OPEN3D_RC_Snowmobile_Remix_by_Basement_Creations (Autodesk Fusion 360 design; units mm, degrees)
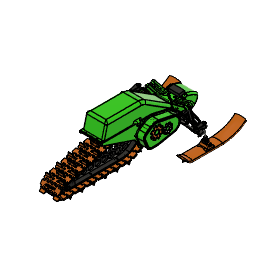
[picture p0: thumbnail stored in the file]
part number: m5x30
part number: m5 locknut (7)
part number: m5x40 (1)
part number: right ski hinge
part number: right steering block
part number: right suspension block
part number: left ski hinge
part number: left outer steering arm
part number: left suspension block
part number: left steering block
part number: right outer steering arm
part number: rear shock mount
part number: track lower ptfe rail 3
part number: left track tensioning block
part number: track hardware
part number: right track tensioning block
part number: right track tensioner
part number: left track tensioner
part number: track lower ptfe rail 2
part number: track spacer right
derived_base_feature "Derived Base Feature1" bodies "Cover", "Frame 1 (1) (1)", "Gears Cover", "Front Cover", "Center Frame", "Top Cover"
extrude "Extrude1" cut of existing geometry blind -2
sketch "Sketch1" plane through (-63, 0, 0) normal (-1, 0, 0) x axis (0, 0, 1)
  line L1 (-98.8345, -25) -> (-74.8119, -25)
  line L2 (-109.7, -25) -> (-113.5655, -25)
  line L3 (-109.7, -28.5) -> (-109.7, -25)
  line L4 (-71.8, -28.5) -> (-109.7, -28.5)
  line L5 (-58.8, 16.6785) -> (-58.8, -15.5)
  line L6 (-30.4282, 38.5) -> (-31.5, 38.5)
  line L7 (14.5718, 38.5) -> (-16.5718, 38.5)
  line L8 (134.5718, 38.5) -> (28.4282, 38.5)
  line L9 (148.1, 42.5) -> (148.1, 38.5)
  line L10 (-31.5, 42.5) -> (148.1, 42.5)
  line L11 (-113.5, 26) -> (-70.1426, 26)
  line L12 (-113.5, 22) -> (-113.5, 26)
  line L13 (-106.8655, 22) -> (-113.5, 22)
  line L14 (-62, -15.1881) -> (-62, -14.4914)
  line L15 (13.9646, 38.5) -> (13.9646, 42.5)
  line L16 (29.9755, 38.5) -> (29.9755, 42.5)
  line L17 (13.5961, 42.5) -> (13.9646, 42.5)
  line L18 (10, 38.5) -> (10, 42.5)
  line L19 (37, 42.5) -> (29.9755, 42.5)
  line L20 (37, 38.5) -> (37, 42.5)
  arc A1 centre (-70.9691, -27.6881) radius 3.5 clockwise from (-72.3848, -24.4872) to (-71.997, -24.3424)
  arc A2 centre (-74.8119, -19) radius 6 clockwise from (-72.3848, -24.4872) to (-74.8119, -25)
  arc A3 centre (-98.8345, -19) radius 6 clockwise from (-98.8345, -25) to (-103.4864, -22.7895)
  arc A4 centre (-106.2, -25) radius 3.5 clockwise from (-108.9136, -22.7895) to (-103.4864, -22.7895)
  arc A5 centre (-113.5655, -19) radius 6 clockwise from (-108.9136, -22.7895) to (-113.5655, -25)
  arc A6 centre (-71.8, -15.5) radius 13 clockwise from (-58.8, -15.5) to (-71.8, -28.5)
  arc A7 centre (-43.8, 16.6785) radius 15 clockwise from (-58.8, 16.6785) to (-56.5241, 24.6219)
  arc A8 centre (-31.5, 9) radius 29.5 clockwise from (-56.5241, 24.6219) to (-31.5, 38.5)
  arc A9 centre (-30.4282, 32.5) radius 6 clockwise from (-30.4282, 38.5) to (-26.0525, 36.6053)
  arc A10 centre (-23.5, 39) radius 3.5 clockwise from (-20.9475, 36.6053) to (-26.0525, 36.6053)
  arc A11 centre (-16.5718, 32.5) radius 6 clockwise from (-20.9475, 36.6053) to (-16.5718, 38.5)
  arc A12 centre (14.5718, 32.5) radius 6 clockwise from (14.5718, 38.5) to (18.9475, 36.6053)
  arc A13 centre (21.5, 39) radius 3.5 clockwise from (24.0525, 36.6053) to (18.9475, 36.6053)
  arc A14 centre (28.4282, 32.5) radius 6 clockwise from (24.0525, 36.6053) to (28.4282, 38.5)
  arc A15 centre (134.5718, 32.5) radius 6 clockwise from (134.5718, 38.5) to (138.9475, 36.6053)
  arc A16 centre (141.5, 39) radius 3.5 clockwise from (144.0558, 36.6088) to (138.9475, 36.6053)
  arc A17 centre (148.4371, 32.5095) radius 6 clockwise from (144.0558, 36.6088) to (148.1, 38.5)
  arc A18 centre (-31.5, 9) radius 33.5 clockwise from (-55.6968, 32.1682) to (-31.5, 42.5)
  arc A19 centre (-70.1426, 46) radius 20 clockwise from (-55.6968, 32.1682) to (-70.1426, 26)
  arc A20 centre (-106.8655, 16) radius 6 clockwise from (-106.8655, 22) to (-102.2136, 19.7895)
  arc A21 centre (-99.5, 22) radius 3.5 clockwise from (-96.7864, 19.7895) to (-102.2136, 19.7895)
  arc A22 centre (-92.1345, 16) radius 6 clockwise from (-96.7864, 19.7895) to (-93.0286, 21.933)
  arc A23 centre (-96.7537, 46.6539) radius 25 clockwise from (-89.9219, 22.6055) to (-93.0286, 21.933)
  arc A24 centre (-83.5, 0) radius 23.5 clockwise from (-89.9219, 22.6055) to (-78.78, 23.0211)
  arc A25 centre (-18.5241, 316.9075) radius 300 clockwise from (-66.3937, 20.7513) to (-78.78, 23.0211)
  arc A26 centre (-67, 17) radius 3.8 clockwise from (-66.3937, 20.7513) to (-63.2685, 17.718)
  arc A27 centre (231.3272, 74.4048) radius 300 clockwise from (-60.63, 5.405) to (-63.2685, 17.718)
  arc A28 centre (-83.5, 0) radius 23.5 clockwise from (-60.63, 5.405) to (-60.8785, -6.3654)
  arc A29 centre (-32, -14.4914) radius 30 clockwise from (-62, -14.4914) to (-60.8785, -6.3654)
  arc A30 centre (-71, -15.1881) radius 9 clockwise from (-62, -15.1881) to (-62.1826, -16.9917)
  arc A31 centre (-66.1014, -16.1901) radius 4 clockwise from (-62.1826, -16.9917) to (-66.2989, -20.1852)
  arc A32 centre (-66.4645, -23.5355) radius 3.3544 clockwise from (-69.5237, -22.1596) to (-66.2989, -20.1852)
  arc A33 centre (-73.1717, -20.5188) radius 4 clockwise from (-69.5237, -22.1596) to (-71.997, -24.3424)
  circle C1 centre (-62.7077, 21.9108) radius 1.4
  circle C2 centre (-23.5, 39) radius 1.4
  circle C3 centre (21.5, 39) radius 1.4
  circle C4 centre (-99.5, 22) radius 1.4
  circle C5 centre (141.5, 39) radius 1.4
  circle C6 centre (-66.4645, -23.5355) radius 1.4
  circle C7 centre (-106.2, -25) radius 1.4
  point P81 (13.9646, 42.5)
  point P82 (13.9646, 38.5)
  point P83 (29.9755, 42.5)
  point P84 (29.9755, 38.5)
  point P85 (13.5961, 42.5)
  point P86 (10, 42.5)
  point P87 (10, 38.5)
  point P88 (37, 42.5)
  point P89 (37, 38.5)
  coincident L10 P81
  coincident L7 P82
  perpendicular L7 L15
  coincident L10 P83
  coincident L8 P84
  perpendicular L8 L16
  coincident L10 P85
  coincident L10 P86
  coincident L7 P87
  perpendicular L7 L18
  coincident L10 P88
  coincident L8 P89
  perpendicular L8 L20
extrude "Extrude2" cut sketch "Sketch1" profile of L7 L8 L10 L15 L16 L17 L18 L19 L20 against normal blind 20
sketch "Sketch2" plane through (0, 38.5, 0) normal (0, -1, 0) x axis (1, 0, 0)
  line L1 (-63, 29.9755) -> (-43, 29.9755)
  line L2 (-63, 28.4282) -> (-63, 29.9755)
  line L3 (-51, 28.4282) -> (-63, 28.4282)
  line L4 (-51, 21.8646) -> (-51, 28.4282)
  line L5 (-51, 21.1354) -> (-51, 21.8646)
  line L6 (-51, 14.5718) -> (-51, 21.1354)
  line L7 (-63, 14.5718) -> (-51, 14.5718)
  line L8 (-63, 13.9646) -> (-63, 14.5718)
  line L9 (-43, 13.9646) -> (-63, 13.9646)
  line L10 (-43, 10) -> (-43, 13.9646)
  line L11 (-63, 10) -> (-43, 10)
  line L12 (-63, -16.5718) -> (-63, 10)
  line L13 (-51, -16.5718) -> (-63, -16.5718)
  line L14 (-51, -23.1354) -> (-51, -16.5718)
  line L15 (-51, -23.8646) -> (-51, -23.1354)
  line L16 (-51, -30.4282) -> (-51, -23.8646)
  line L17 (-63, -30.4282) -> (-51, -30.4282)
  line L18 (-63, -31.5) -> (-63, -30.4282)
  line L19 (13, -31.5) -> (-63, -31.5)
  line L20 (13, -8.9627) -> (13, -31.5)
  line L21 (9, -8.9627) -> (13, -8.9627)
  curve K1 (6, -2.7177) -> (9, -8.9627)
  line L22 (6, -2.6231) -> (6, -2.7177)
  curve K2 (9, 3.6219) -> (6, -2.6231)
  line L23 (13, 3.6219) -> (9, 3.6219)
  line L24 (13, 148.1) -> (13, 3.6219)
  line L25 (-51.1685, 148.1) -> (13, 148.1)
  curve K3 (-51, 148.0242) -> (-51.1685, 148.1)
  line L26 (-51, 141.8651) -> (-51, 148.0242)
  line L27 (-51, 141.1354) -> (-51, 141.8651)
  line L28 (-51, 134.5718) -> (-51, 141.1354)
  line L29 (-63, 134.5718) -> (-51, 134.5718)
  line L30 (-63, 37) -> (-63, 134.5718)
  line L31 (-43, 37) -> (-63, 37)
  line L32 (-43, 29.9755) -> (-43, 37)
  line L33 (-43, 11.9823) -> (-43, 33.4878)
  line L34 (-46, 11.9823) -> (-43, 11.9823)
  line L35 (-46, 33.4878) -> (-46, 11.9823)
  line L36 (-43, 33.4878) -> (-46, 33.4878)
  circle C1 centre (-5, 144.6) radius 1.4
  circle C2 centre (-45, 144.6) radius 1.4
  point P40 (-43, 11.9823)
  point P39 (-43, 33.4878)
  perpendicular L33 L34
  parallel L33 L35
  parallel L34 L36
  midpoint L10 P40
  perpendicular L9 L33
  midpoint L32 P39
extrude "Extrude3" cut sketch "Sketch2" profile of L1 L9 L10 L32 L33 L34 L35 L36 against normal blind 4 bodies "Center Frame"
move "Move1"
combine "Combine1" bodies "Center Frame"
extrude "Extrude4" add of existing geometry blind 3
extrude "Extrude5" add of existing geometry blind 17
derived_base_feature "Derived Base Feature1"
derived_base_feature "Derived Base Feature1"
derived_base_feature "Derived Base Feature1"
derived_base_feature "Derived Base Feature1" bodies "Body1"
derived_base_feature "Derived Base Feature1" bodies "Body1"
derived_base_feature "Derived Base Feature1" bodies "Body1"
derived_base_feature "Derived Base Feature1" bodies "Body1"
derived_base_feature "Derived Base Feature1" bodies "Body1"
derived_base_feature "Derived Base Feature1" bodies "Body1"
derived_base_feature "Derived Base Feature1" bodies "Body1"
derived_base_feature "Derived Base Feature1" bodies "Body1"
derived_base_feature "Derived Base Feature1" bodies "Body1"
derived_base_feature "Derived Base Feature1" bodies "Body1"
derived_base_feature "Derived Base Feature1" bodies "Body1"
derived_base_feature "Derived Base Feature1" bodies "Body1"
derived_base_feature "Derived Base Feature1" bodies "Body1"
derived_base_feature "Derived Base Feature1" bodies "Body1"
derived_base_feature "Derived Base Feature1" bodies "Body1"
derived_base_feature "Derived Base Feature1" bodies "Body1"
derived_base_feature "Derived Base Feature1" bodies "Body1"
derived_base_feature "Derived Base Feature1" bodies "Body1"
derived_base_feature "Derived Base Feature1" bodies "Body1"
derived_base_feature "Derived Base Feature1" bodies "Body1"
derived_base_feature "Derived Base Feature1" bodies "Body1"
derived_base_feature "Derived Base Feature1" bodies "Body1"
derived_base_feature "Derived Base Feature1" bodies "Body1"
derived_base_feature "Derived Base Feature1" bodies "Body1"
derived_base_feature "Derived Base Feature1" bodies "Body1"
derived_base_feature "Derived Base Feature1" bodies "Body1"
derived_base_feature "Derived Base Feature1" bodies "Body1"
derived_base_feature "Derived Base Feature1" bodies "Body1"
derived_base_feature "Derived Base Feature1" bodies "Body1"
derived_base_feature "Derived Base Feature1" bodies "Body1"
derived_base_feature "Derived Base Feature1" bodies "Body1"
derived_base_feature "Derived Base Feature1" bodies "Body1"
derived_base_feature "Derived Base Feature1" bodies "Body1"
derived_base_feature "Derived Base Feature1" bodies "Body1"
derived_base_feature "Derived Base Feature1" bodies "Body1"
derived_base_feature "Derived Base Feature1" bodies "Body1"
derived_base_feature "Derived Base Feature1" bodies "Body1"
derived_base_feature "Derived Base Feature1" bodies "Body1"
derived_base_feature "Derived Base Feature1" bodies "Body1"
derived_base_feature "Derived Base Feature1" bodies "Body1"
derived_base_feature "Derived Base Feature1" bodies "Body1"
derived_base_feature "Derived Base Feature1" bodies "Body1"
derived_base_feature "Derived Base Feature1" bodies "Body1"
derived_base_feature "Derived Base Feature1" bodies "Body1"
derived_base_feature "Derived Base Feature1" bodies "Body1"
derived_base_feature "Derived Base Feature1" bodies "Body1"
derived_base_feature "Derived Base Feature1" bodies "Body1"
derived_base_feature "Derived Base Feature1" bodies "Body1"
derived_base_feature "Derived Base Feature1" bodies "Body1"
derived_base_feature "Derived Base Feature1" bodies "Body1"
derived_base_feature "Derived Base Feature1"
derived_base_feature "Derived Base Feature1" bodies "Body1"
derived_base_feature "Derived Base Feature1" bodies "Body1"
derived_base_feature "Derived Base Feature1" bodies "Body1"
derived_base_feature "Derived Base Feature1" bodies "Body1"
derived_base_feature "Derived Base Feature1"
derived_base_feature "Derived Base Feature1" bodies "Body1"
derived_base_feature "Derived Base Feature1" bodies "Body1"
derived_base_feature "Derived Base Feature1" bodies "Body1"
derived_base_feature "Derived Base Feature1" bodies "Body1"
derived_base_feature "Derived Base Feature1" bodies "Body1"
derived_base_feature "Derived Base Feature1" bodies "Body1"
derived_base_feature "Derived Base Feature1" bodies "Body1"
derived_base_feature "Derived Base Feature1" bodies "Body1"
derived_base_feature "Derived Base Feature1" bodies "Body1"
derived_base_feature "Derived Base Feature1" bodies "Body1"
derived_base_feature "Derived Base Feature1" bodies "Body1"
derived_base_feature "Derived Base Feature1" bodies "Body1"
derived_base_feature "Derived Base Feature1" bodies "Body1"
derived_base_feature "Derived Base Feature1" bodies "Body1"
derived_base_feature "Derived Base Feature1" bodies "Body1"
derived_base_feature "Derived Base Feature1" bodies "Body1"
derived_base_feature "Derived Base Feature1" bodies "Body1"
derived_base_feature "Derived Base Feature1" bodies "Body1"
derived_base_feature "Derived Base Feature1" bodies "Body1"
derived_base_feature "Derived Base Feature1" bodies "Body1"
derived_base_feature "Derived Base Feature1" bodies "Body1"
derived_base_feature "Derived Base Feature1" bodies "Body1"
derived_base_feature "Derived Base Feature1" bodies "Body1"
derived_base_feature "Derived Base Feature1" bodies "Body1"
derived_base_feature "Derived Base Feature1" bodies "Body1"
derived_base_feature "Derived Base Feature1" bodies "Body1"
derived_base_feature "Derived Base Feature1" bodies "Body1"
derived_base_feature "Derived Base Feature1" bodies "Body1"
derived_base_feature "Derived Base Feature1" bodies "Body1"
derived_base_feature "Derived Base Feature1" bodies "Body1"
derived_base_feature "Derived Base Feature1" bodies "Body1"
derived_base_feature "Derived Base Feature1" bodies "Body1"
derived_base_feature "Derived Base Feature1" bodies "Body1"
derived_base_feature "Derived Base Feature1" bodies "Body1"
derived_base_feature "Derived Base Feature1" bodies "Body1"
derived_base_feature "Derived Base Feature1"
derived_base_feature "Derived Base Feature1" bodies "Body1"
derived_base_feature "Derived Base Feature1" bodies "Body1"
derived_base_feature "Derived Base Feature1" bodies "Body1"
derived_base_feature "Derived Base Feature1" bodies "Body1"
derived_base_feature "Derived Base Feature1" bodies "Body1"
derived_base_feature "Derived Base Feature1" bodies "Body1"
derived_base_feature "Derived Base Feature1" bodies "Body1"
derived_base_feature "Derived Base Feature1" bodies "Body1"
derived_base_feature "Derived Base Feature1" bodies "Body1"
derived_base_feature "Derived Base Feature1" bodies "Body1"
derived_base_feature "Derived Base Feature1" bodies "Body1"
place_component sketch "Sketch3"
derived_base_feature "Derived Base Feature1" sketch "Sketch3" bodies "Body1"
derived_base_feature "Derived Base Feature1" bodies "Body1"
derived_base_feature "Derived Base Feature1" bodies "Body1"
derived_base_feature "Derived Base Feature1" bodies "Body1"
derived_base_feature "Derived Base Feature1" bodies "Body1"
derived_base_feature "Derived Base Feature1"
derived_base_feature "Derived Base Feature1" bodies "Body1"
derived_base_feature "Derived Base Feature1" bodies "Body1"
derived_base_feature "Derived Base Feature1" bodies "Body1"
derived_base_feature "Derived Base Feature1" bodies "Body1"
derived_base_feature "Derived Base Feature1" bodies "Body1"
derived_base_feature "Derived Base Feature1" bodies "Body1"
derived_base_feature "Derived Base Feature1" bodies "Body1"
derived_base_feature "Derived Base Feature1" bodies "Body1"
derived_base_feature "Derived Base Feature1" bodies "Body1"
derived_base_feature "Derived Base Feature1" bodies "Body1"
derived_base_feature "Derived Base Feature1" bodies "Body1"
derived_base_feature "Derived Base Feature1" bodies "Body1"
derived_base_feature "Derived Base Feature1" bodies "Body1"
derived_base_feature "Derived Base Feature1" bodies "Body1"
derived_base_feature "Derived Base Feature1" bodies "Body1"
derived_base_feature "Derived Base Feature1" bodies "Body1"
derived_base_feature "Derived Base Feature1" bodies "Body1"
derived_base_feature "Derived Base Feature1" bodies "Body1"
derived_base_feature "Derived Base Feature1" bodies "Body1"
derived_base_feature "Derived Base Feature1" bodies "Body1"
derived_base_feature "Derived Base Feature1" bodies "Body1"
derived_base_feature "Derived Base Feature1" bodies "Body1"
derived_base_feature "Derived Base Feature1" bodies "Body1"
derived_base_feature "Derived Base Feature1" bodies "Body1"
derived_base_feature "Derived Base Feature1" bodies "Body1"
derived_base_feature "Derived Base Feature1" bodies "Body1"
derived_base_feature "Derived Base Feature1" bodies "Body1"
derived_base_feature "Derived Base Feature1" bodies "Body1"
derived_base_feature "Derived Base Feature1" bodies "Body1"
derived_base_feature "Derived Base Feature1" bodies "Body1"
derived_base_feature "Derived Base Feature1" bodies "Body1"
derived_base_feature "Derived Base Feature1" bodies "Body1"
derived_base_feature "Derived Base Feature1" bodies "Body1"
derived_base_feature "Derived Base Feature1" bodies "Body1"
derived_base_feature "Derived Base Feature1" bodies "Body1"
derived_base_feature "Derived Base Feature1" bodies "Body1"
derived_base_feature "Derived Base Feature1" bodies "Body1"
derived_base_feature "Derived Base Feature1" bodies "Body1"
derived_base_feature "Derived Base Feature1" bodies "Body1"
derived_base_feature "Derived Base Feature1" bodies "Body1"
derived_base_feature "Derived Base Feature1" bodies "Body1"
derived_base_feature "Derived Base Feature1" bodies "Body1"
derived_base_feature "Derived Base Feature1" bodies "Body1"
derived_base_feature "Derived Base Feature1" bodies "Body1"
derived_base_feature "Derived Base Feature1" bodies "Body1"
derived_base_feature "Derived Base Feature1" bodies "Body1"
derived_base_feature "Derived Base Feature1" bodies "Body1"
derived_base_feature "Derived Base Feature1" bodies "Body1"
derived_base_feature "Derived Base Feature1" bodies "Body1"
derived_base_feature "Derived Base Feature1" bodies "Body1"
derived_base_feature "Derived Base Feature1" bodies "Body1"
derived_base_feature "Derived Base Feature1" bodies "Body1"
derived_base_feature "Derived Base Feature1" bodies "Body1"
derived_base_feature "Derived Base Feature1" bodies "Body1"
derived_base_feature "Derived Base Feature1"
derived_base_feature "Derived Base Feature1" bodies "Body1"
derived_base_feature "Derived Base Feature1" bodies "Body1"
derived_base_feature "Derived Base Feature1" bodies "Body1"
derived_base_feature "Derived Base Feature1" bodies "Body1"
derived_base_feature "Derived Base Feature1" bodies "Body1"
derived_base_feature "Derived Base Feature1" bodies "Body1"
derived_base_feature "Derived Base Feature1" bodies "Body1"
derived_base_feature "Derived Base Feature1" bodies "Body1"
derived_base_feature "Derived Base Feature1" bodies "Body1"
derived_base_feature "Derived Base Feature1" bodies "Body1"
derived_base_feature "Derived Base Feature1" bodies "Body1"
derived_base_feature "Derived Base Feature1" bodies "Body1"
derived_base_feature "Derived Base Feature1" bodies "Body1"
derived_base_feature "Derived Base Feature1" bodies "Body1"
derived_base_feature "Derived Base Feature1" bodies "Body1"
derived_base_feature "Derived Base Feature1" bodies "Body1"
derived_base_feature "Derived Base Feature1"
derived_base_feature "Derived Base Feature1" bodies "Body1"
derived_base_feature "Derived Base Feature1" bodies "Body1"
derived_base_feature "Derived Base Feature1" bodies "Body1"
derived_base_feature "Derived Base Feature1" bodies "Body1"
derived_base_feature "Derived Base Feature1" bodies "Body1"
derived_base_feature "Derived Base Feature1" bodies "Body1"
derived_base_feature "Derived Base Feature1" bodies "Body1"
derived_base_feature "Derived Base Feature1" bodies "Body1"
derived_base_feature "Derived Base Feature1" bodies "Body1"
derived_base_feature "Derived Base Feature1" bodies "Body1"
derived_base_feature "Derived Base Feature1" bodies "Body1"
derived_base_feature "Derived Base Feature1" bodies "Body1"
derived_base_feature "Derived Base Feature1" bodies "Body1"
derived_base_feature "Derived Base Feature1" bodies "Body1"
derived_base_feature "Derived Base Feature1" bodies "Body1"
derived_base_feature "Derived Base Feature1" bodies "Body1"
sketch "Sketch3" plane through (0, 32.5, 0) normal (0, 1, 0) x axis (-1, 0, 0)
  line L1 (53, -116.699) -> (46.1312, -121.5476)
  line L2 (53, -113.4468) -> (53, -116.699)
  line L3 (-3, -113.4468) -> (53, -113.4468)
  line L4 (-3, -116.699) -> (-3, -113.4468)
  line L5 (3.8688, -121.5476) -> (-3, -116.699)
  arc A1 centre (25, -135.1) radius 3.4 clockwise from (21.7517, -134.0956) to (28.2483, -134.0956)
  arc A2 centre (39.8661, -137.1) radius 12 clockwise from (28.2483, -134.0956) to (39.3465, -125.1113)
  arc A3 centre (39.0001, -117.1188) radius 8 clockwise from (44.6206, -122.8117) to (39.3465, -125.1113)
  arc A4 centre (53.0514, -131.3512) radius 12 clockwise from (44.6206, -122.8117) to (46.1312, -121.5476)
  arc A5 centre (-3.0514, -131.3512) radius 12 clockwise from (3.8688, -121.5476) to (5.3794, -122.8117)
  arc A6 centre (10.9999, -117.1188) radius 8 clockwise from (10.6535, -125.1113) to (5.3794, -122.8117)
  arc A7 centre (10.1339, -137.1) radius 12 clockwise from (10.6535, -125.1113) to (21.7517, -134.0956)
  circle C1 centre (25, -135.1) radius 1.4
  concentric A1 C1
  dimension "d11" diameter C1 = 2.8
extrude "Extrude6" cut sketch "Sketch3" profile of C1 against normal blind 20
derived_base_feature "Derived Base Feature2" bodies "8mm Aluminium Pipe", "Motor", "Big Gear", "Rear Sprocket Arm Left"
derived_base_feature "Derived Base Feature3" bodies "Small Motor Gear"
extrude "Extrude7" new body of existing geometry blind 3 bodies "Left Center Frame"
move "Move2"
extrude "Extrude8" new body of existing geometry blind 3
move "Move3"
sketch "Sketch4" plane through (-63, 0, 0) normal (-1, 0, 0) x axis (0, 0, 1)
  line L1 (134.5718, 38.5) -> (41.4282, 38.5)
  line L2 (148.1, 42.5) -> (148.1, 38.5)
  line L3 (-31.5, 42.5) -> (148.1, 42.5)
  line L4 (-113.5, 26) -> (-70.1426, 26)
  line L5 (-113.5, 22) -> (-113.5, 26)
  line L6 (-106.8655, 22) -> (-113.5, 22)
  line L7 (-62, -15.1881) -> (-62, -14.4914)
  line L8 (-98.8345, -25) -> (-74.8119, -25)
  line L9 (-109.7, -25) -> (-113.5655, -25)
  line L10 (-109.7, -28.5) -> (-109.7, -25)
  line L11 (-71.8, -28.5) -> (-109.7, -28.5)
  line L12 (-58.8, 16.6785) -> (-58.8, -15.5)
  line L13 (-30.4282, 38.5) -> (-31.5, 38.5)
  line L14 (27.5718, 38.5) -> (-16.5718, 38.5)
  line L15 (-28.044, 38.006) -> (148.1, 38.5)
  circle C1 centre (-106.2, -25) radius 1.4
  circle C2 centre (-66.4645, -23.5355) radius 1.4
  circle C3 centre (-99.5, 22) radius 1.4
  circle C4 centre (-23.5, 39) radius 1.4
  circle C5 centre (-62.7077, 21.9108) radius 1.4
  circle C6 centre (34.5, 39) radius 1.4
  arc A1 centre (134.5718, 32.5) radius 6 clockwise from (134.5718, 38.5) to (138.9475, 36.6053)
  arc A2 centre (141.5, 39) radius 3.5 clockwise from (144.0558, 36.6088) to (138.9475, 36.6053)
  arc A3 centre (148.4371, 32.5095) radius 6 clockwise from (144.0558, 36.6088) to (148.1, 38.5)
  arc A4 centre (-31.5, 9) radius 33.5 clockwise from (-55.6968, 32.1682) to (-31.5, 42.5)
  arc A5 centre (-70.1426, 46) radius 20 clockwise from (-55.6968, 32.1682) to (-70.1426, 26)
  arc A6 centre (-106.8655, 16) radius 6 clockwise from (-106.8655, 22) to (-102.2136, 19.7895)
  arc A7 centre (-99.5, 22) radius 3.5 clockwise from (-96.7864, 19.7895) to (-102.2136, 19.7895)
  arc A8 centre (-92.1345, 16) radius 6 clockwise from (-96.7864, 19.7895) to (-93.0286, 21.933)
  arc A9 centre (-96.7537, 46.6539) radius 25 clockwise from (-89.9219, 22.6055) to (-93.0286, 21.933)
  arc A10 centre (-83.5, 0) radius 23.5 clockwise from (-89.9219, 22.6055) to (-78.78, 23.0211)
  arc A11 centre (-18.5241, 316.9075) radius 300 clockwise from (-66.3937, 20.7513) to (-78.78, 23.0211)
  arc A12 centre (-67, 17) radius 3.8 clockwise from (-66.3937, 20.7513) to (-63.2685, 17.718)
  arc A13 centre (231.3272, 74.4048) radius 300 clockwise from (-60.63, 5.405) to (-63.2685, 17.718)
  arc A14 centre (-83.5, 0) radius 23.5 clockwise from (-60.63, 5.405) to (-60.8785, -6.3654)
  arc A15 centre (-32, -14.4914) radius 30 clockwise from (-62, -14.4914) to (-60.8785, -6.3654)
  arc A16 centre (-71, -15.1881) radius 9 clockwise from (-62, -15.1881) to (-62.1826, -16.9917)
  arc A17 centre (-66.1014, -16.1901) radius 4 clockwise from (-62.1826, -16.9917) to (-66.2989, -20.1852)
  arc A18 centre (-66.4645, -23.5355) radius 3.3544 clockwise from (-69.5237, -22.1596) to (-66.2989, -20.1852)
  arc A19 centre (-73.1717, -20.5188) radius 4 clockwise from (-69.5237, -22.1596) to (-71.997, -24.3424)
  arc A20 centre (-70.9691, -27.6881) radius 3.5 clockwise from (-72.3848, -24.4872) to (-71.997, -24.3424)
  arc A21 centre (-74.8119, -19) radius 6 clockwise from (-72.3848, -24.4872) to (-74.8119, -25)
  arc A22 centre (-98.8345, -19) radius 6 clockwise from (-98.8345, -25) to (-103.4864, -22.7895)
  arc A23 centre (-106.2, -25) radius 3.5 clockwise from (-108.9136, -22.7895) to (-103.4864, -22.7895)
  arc A24 centre (-113.5655, -19) radius 6 clockwise from (-108.9136, -22.7895) to (-113.5655, -25)
  arc A25 centre (-71.8, -15.5) radius 13 clockwise from (-58.8, -15.5) to (-71.8, -28.5)
  arc A26 centre (-43.8, 16.6785) radius 15 clockwise from (-58.8, 16.6785) to (-56.5241, 24.6219)
  arc A27 centre (-31.5, 9) radius 29.5 clockwise from (-56.5241, 24.6219) to (-31.5, 38.5)
  arc A28 centre (-30.4282, 32.5) radius 6 clockwise from (-30.4282, 38.5) to (-26.0525, 36.6053)
  arc A29 centre (-23.5, 39) radius 3.5 clockwise from (-20.9475, 36.6053) to (-26.0525, 36.6053)
  arc A30 centre (-16.5718, 32.5) radius 6 clockwise from (-20.9475, 36.6053) to (-16.5718, 38.5)
  arc A31 centre (27.5718, 32.5) radius 6 clockwise from (27.5718, 38.5) to (31.9475, 36.6053)
  arc A32 centre (34.5, 39) radius 3.5 clockwise from (37.0525, 36.6053) to (31.9475, 36.6053)
  arc A33 centre (41.4282, 32.5) radius 6 clockwise from (37.0525, 36.6053) to (41.4282, 38.5)
  circle C7 centre (141.5, 39) radius 1.4
  point P14 (148.1, 38.5)
  point P81 (148.1, 38.5)
  point P82 (-28.044, 38.006)
  coincident P14 P81
  midpoint A28 P82
extrude "Extrude9" new body sketch "Sketch4" profile of C1 C2 C3 C4 C5 C6 L1 A1 L2 L3 A4 A5 L4 L5 L6 A6 A7 A8 A9 A10 A11 A12 A13 A14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 along normal blind 3
combine "Combine2"
delete_face "DeleteFace1"
delete_face "DeleteFace2"
delete_face "DeleteFace3"
extrude "Extrude10" new body of existing geometry blind 4
combine "Combine3"
delete_face "DeleteFace4"
delete_face "DeleteFace5"
delete_face "DeleteFace6"
delete_face "DeleteFace7"
offset_faces "OffsetFaces1" distance -0.2
offset_faces "OffsetFaces2" distance -0.2
sketch "Sketch5" plane through (-70, 0, 0) normal (-1, 0, 0) x axis (0, 0, 1)
  line L1 (11.6299, 43.5) -> (21.6299, 43.5)
  line L2 (11.6299, 42.5) -> (11.6299, 43.5)
  line L3 (11.6299, 36.5) -> (11.6299, 42.5)
  line L4 (21.6299, 42.5) -> (21.6299, 36.5)
  line L5 (21.6299, 43.5) -> (21.6299, 42.5)
  arc A1 centre (16.6299, 36.5) radius 5 clockwise from (21.6299, 36.5) to (11.6299, 36.5)
  circle C1 centre (16.6299, 36.5) radius 1.4
  circle C2 centre (16.6299, 36.5) radius 1.4
  concentric A1 C2
extrude "Extrude11" cut sketch "Sketch5" profile of C1 C2 against normal blind 7
offset_faces "OffsetFaces3" distance -0.2
chamfer "Chamfer1" distance 1
sketch "Sketch6" plane through (-66, 0, 0) normal (-1, 0, 0) x axis (0, 0, 1)
  line L1 (-113.5, 26) -> (-109.4918, 26)
  line L2 (-113.5, 22) -> (-113.5, 26)
  line L3 (-106.8655, 22) -> (-113.5, 22)
  line L4 (-62, -15.1881) -> (-62, -14.4914)
  line L5 (-98.8345, -25) -> (-74.8119, -25)
  line L6 (-109.7, -25) -> (-113.5655, -25)
  line L7 (-109.7, -28.5) -> (-109.7, -25)
  line L8 (-106.5775, -28.5) -> (-109.7, -28.5)
  line L9 (-33.4923, -42.3571) -> (-98.7142, -29.2805)
  line L10 (3.6317, -43.2) -> (-25, -43.2)
  line L11 (21.7171, -15.114) -> (12.9046, -36.9434)
  line L12 (145.3671, 33.5873) -> (33.9274, -3.6309)
  line L13 (148.1, 42.5) -> (148.1, 37.3813)
  line L14 (-31.5, 42.5) -> (148.1, 42.5)
  line L15 (-109.4918, 26) -> (-38.7609, 41.7037)
  line L16 (-113.5, -24.9996) -> (-113.5, 26)
  circle C1 centre (34.5, 39) radius 2.6
  arc A1 centre (-106.8655, 16) radius 6 clockwise from (-106.8655, 22) to (-102.2136, 19.7895)
  arc A2 centre (-99.5, 22) radius 3.5 clockwise from (-96.7864, 19.7895) to (-102.2136, 19.7895)
  arc A3 centre (-92.1345, 16) radius 6 clockwise from (-96.7864, 19.7895) to (-93.0286, 21.933)
  arc A4 centre (-96.7537, 46.6539) radius 25 clockwise from (-89.9219, 22.6055) to (-93.0286, 21.933)
  arc A5 centre (-83.5, 0) radius 23.5 clockwise from (-89.9219, 22.6055) to (-78.78, 23.0211)
  arc A6 centre (-18.5241, 316.9075) radius 300 clockwise from (-66.3937, 20.7513) to (-78.78, 23.0211)
  arc A7 centre (-67, 17) radius 3.8 clockwise from (-66.3937, 20.7513) to (-63.2685, 17.718)
  arc A8 centre (231.3272, 74.4048) radius 300 clockwise from (-60.63, 5.405) to (-63.2685, 17.718)
  arc A9 centre (-83.5, 0) radius 23.5 clockwise from (-60.63, 5.405) to (-60.8785, -6.3654)
  arc A10 centre (-32, -14.4914) radius 30 clockwise from (-62, -14.4914) to (-60.8785, -6.3654)
  arc A11 centre (-71, -15.1881) radius 9 clockwise from (-62, -15.1881) to (-62.1826, -16.9917)
  arc A12 centre (-66.1014, -16.1901) radius 4 clockwise from (-62.1826, -16.9917) to (-66.2989, -20.1852)
  arc A13 centre (-66.4645, -23.5355) radius 3.3544 clockwise from (-69.5237, -22.1596) to (-66.2989, -20.1852)
  arc A14 centre (-73.1717, -20.5188) radius 4 clockwise from (-69.5237, -22.1596) to (-71.997, -24.3424)
  arc A15 centre (-70.9691, -27.6881) radius 3.5 clockwise from (-72.3848, -24.4872) to (-71.997, -24.3424)
  arc A16 centre (-74.8119, -19) radius 6 clockwise from (-72.3848, -24.4872) to (-74.8119, -25)
  arc A17 centre (-98.8345, -19) radius 6 clockwise from (-98.8345, -25) to (-103.4864, -22.7895)
  arc A18 centre (-106.2, -25) radius 3.5 clockwise from (-108.9136, -22.7895) to (-103.4864, -22.7895)
  arc A19 centre (-113.5655, -19) radius 6 clockwise from (-108.9136, -22.7895) to (-113.5655, -25)
  arc A20 centre (-106.5775, -68.5) radius 40 clockwise from (-106.5775, -28.5) to (-98.7142, -29.2805)
  arc A21 centre (-25, 0) radius 43.2 clockwise from (-25, -43.2) to (-33.4923, -42.3571)
  arc A22 centre (3.6317, -33.2) radius 10 clockwise from (12.9046, -36.9434) to (3.6317, -43.2)
  arc A23 centre (40.2629, -22.6009) radius 20 clockwise from (21.7171, -15.114) to (33.9274, -3.6309)
  arc A24 centre (144.1, 37.3813) radius 4 clockwise from (148.1, 37.3813) to (145.3671, 33.5873)
  arc A25 centre (-31.5, 9) radius 33.5 clockwise from (-38.7609, 41.7037) to (-31.5, 42.5)
  circle C2 centre (-99.5, 22) radius 1.4
  circle C3 centre (-62.7077, 21.9108) radius 1.4
  circle C4 centre (-106.2, -25) radius 1.4
  circle C5 centre (-66.4645, -23.5355) radius 1.4
  circle C6 centre (-1, -30) radius 2.6
  circle C7 centre (16, 5) radius 2.6
  circle C8 centre (2, 5) radius 2.6
  circle C9 centre (-10, -22) radius 2.6
  circle C10 centre (16.6299, 36.5) radius 1.4
  circle C11 centre (-23.5, 39) radius 2.6
  circle C12 centre (141.5, 39) radius 2.6
  point P4 (-113.5, 26)
  point P75 (-113.5, 26)
  point P76 (-113.5, -24.9996)
  vertical L16
  coincident P4 P75
  coincident A19 P76
extrude "Extrude12" new body sketch "Sketch6" profile of L3 A1 A2 A3 A4 A5 A6 A7 A8 A9 A10 L4 A11 A12 A13 A14 A15 A16 L5 A17 A18 A19 L16 against normal blind 3
combine "Combine4"
offset_faces "OffsetFaces4" distance -0.2
offset_faces "OffsetFaces5" distance -0.2
offset_faces "OffsetFaces6" distance -0.2
offset_faces "OffsetFaces7" distance -0.2
chamfer "Chamfer2" distance 1
sketch "Sketch7" plane through (-66, 0, 0) normal (-1, 0, 0) x axis (0, 0, 1)
  line L1 (-113.5, 26) -> (-109.4918, 26)
  line L2 (-113.5, -24.9996) -> (-113.5, 26)
  line L3 (-109.7, -25) -> (-113.5655, -25)
  line L4 (-109.7, -28.5) -> (-109.7, -25)
  line L5 (-106.5775, -28.5) -> (-109.7, -28.5)
  line L6 (-33.4923, -42.3571) -> (-98.7142, -29.2805)
  line L7 (3.6317, -43.2) -> (-25, -43.2)
  line L8 (21.7171, -15.114) -> (12.9046, -36.9434)
  line L9 (145.3671, 33.5873) -> (33.9274, -3.6309)
  line L10 (148.1, 42.5) -> (148.1, 37.3813)
  line L11 (-31.5, 42.5) -> (148.1, 42.5)
  line L12 (-109.4918, 26) -> (-38.7609, 41.7037)
  line L13 (-106.5775, -28.4) -> (-109.6, -28.4)
  line L14 (-33.4726, -42.259) -> (-98.6946, -29.1824)
  line L15 (3.6317, -43.1) -> (-25, -43.1)
  line L16 (21.6244, -15.0766) -> (12.8119, -36.906)
  line L17 (145.3354, 33.6821) -> (33.8957, -3.536)
  line L18 (148, 42.4) -> (148, 37.3813)
  line L19 (-31.5, 42.4) -> (148, 42.4)
  line L20 (-109.4808, 25.9) -> (-38.7392, 41.606)
  line L21 (-113.4, 25.9) -> (-109.4808, 25.9)
  line L22 (-113.4, -24.9) -> (-113.4, 25.9)
  line L23 (-109.6, -24.9) -> (-113.4, -24.9)
  line L24 (-109.6, -28.4) -> (-109.6, -24.9)
  line L25 (-113.5, -24.9) -> (-113, -24.9)
  line L26 (-109.6, -28.5) -> (-109.6, -27.4513)
  circle C1 centre (-66.4645, -23.5355) radius 2.6
  circle C2 centre (-99.5, 22) radius 2.6
  circle C3 centre (34.5, 39) radius 2.6
  arc A1 centre (-113.5655, -19) radius 6 clockwise from (-113.5, -24.9996) to (-113.5655, -25)
  arc A2 centre (-106.5775, -68.5) radius 40 clockwise from (-106.5775, -28.5) to (-98.7142, -29.2805)
  arc A3 centre (-25, 0) radius 43.2 clockwise from (-25, -43.2) to (-33.4923, -42.3571)
  arc A4 centre (3.6317, -33.2) radius 10 clockwise from (12.9046, -36.9434) to (3.6317, -43.2)
  arc A5 centre (40.2629, -22.6009) radius 20 clockwise from (21.7171, -15.114) to (33.9274, -3.6309)
  arc A6 centre (144.1, 37.3813) radius 4 clockwise from (148.1, 37.3813) to (145.3671, 33.5873)
  arc A7 centre (-31.5, 9) radius 33.5 clockwise from (-38.7609, 41.7037) to (-31.5, 42.5)
  circle C4 centre (-1, -30) radius 2.6
  circle C5 centre (16, 5) radius 2.6
  circle C6 centre (2, 5) radius 2.6
  circle C7 centre (-10, -22) radius 2.6
  circle C8 centre (16.6299, 36.5) radius 1.4
  circle C9 centre (-23.5, 39) radius 2.6
  circle C10 centre (141.5, 39) radius 2.6
  circle C11 centre (-62.7077, 21.9108) radius 2.6
  circle C12 centre (-106.2, -25) radius 2.6
  arc A8 centre (-106.5775, -68.5) radius 40.1 clockwise from (-106.5775, -28.4) to (-98.6946, -29.1824)
  arc A9 centre (-25, 0) radius 43.1 clockwise from (-25, -43.1) to (-33.4726, -42.259)
  arc A10 centre (3.6317, -33.2) radius 9.9 clockwise from (12.8119, -36.906) to (3.6317, -43.1)
  arc A11 centre (40.2629, -22.6009) radius 20.1 clockwise from (21.6244, -15.0766) to (33.8957, -3.536)
  arc A12 centre (144.1, 37.3813) radius 3.9 clockwise from (148, 37.3813) to (145.3354, 33.6821)
  arc A13 centre (-31.5, 9) radius 33.4 clockwise from (-38.7392, 41.606) to (-31.5, 42.4)
  point P64 (-113, -24.9)
  point P65 (-113.5, -24.9)
  point P66 (-109.6, -27.4513)
  point P67 (-109.6, -28.5)
  coincident L23 P64
  coincident L2 P65
  perpendicular L2 L25
  coincident L24 P66
  coincident L5 P67
  perpendicular L5 L26
  dimension "d37" = -0.1
extrude "Extrude13" cut sketch "Sketch7" profile of L2 A1 L3 L4 L5 L23 L24 L25 L26 against normal blind 3.7
derived_base_feature "Derived Base Feature4" bodies "Front Sprocket 2", "Front Sprocket 1", "Front Sprocket Spacer 2"
copy_paste_bodies "CopyPasteBodies1"
move "Move4"
extrude "Extrude14" cut of existing geometry blind -0.1
extrude "Extrude15" cut of existing geometry blind -0.1
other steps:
extrude "Extrude1" cut sketch "Sketch3" profile of C1 against normal blind 20
base_feature "Base Feature" bodies "Body16", "Front Sprocket Spacer 1"
create_component "CreateComponent81"
create_component "CreateComponent85"
create_component "CreateComponent234"
create_component "CreateComponent2"
create_component "CreateComponent1"
create_component "CreateComponent1"
create_component "CreateComponent2"
create_component "CreateComponent3"
create_component "CreateComponent4"
create_component "CreateComponent5"
create_component "CreateComponent6"
create_component "CreateComponent7"
create_component "CreateComponent8"
create_component "CreateComponent9"
create_component "CreateComponent10"
create_component "CreateComponent11"
create_component "CreateComponent12"
create_component "CreateComponent13"
create_component "CreateComponent14"
create_component "CreateComponent15"
create_component "CreateComponent16"
create_component "CreateComponent17"
create_component "CreateComponent18"
create_component "CreateComponent19"
create_component "CreateComponent20"
create_component "CreateComponent21"
create_component "CreateComponent22"
create_component "CreateComponent23"
create_component "CreateComponent24"
create_component "CreateComponent25"
create_component "CreateComponent26"
create_component "CreateComponent27"
create_component "CreateComponent28"
create_component "CreateComponent29"
create_component "CreateComponent30"
create_component "CreateComponent31"
create_component "CreateComponent32"
create_component "CreateComponent33"
create_component "CreateComponent34"
create_component "CreateComponent35"
create_component "CreateComponent36"
create_component "CreateComponent37"
create_component "CreateComponent38"
create_component "CreateComponent39"
create_component "CreateComponent40"
create_component "CreateComponent41"
create_component "CreateComponent42"
create_component "CreateComponent2"
create_component "CreateComponent3"
create_component "CreateComponent4"
create_component "CreateComponent5"
create_component "CreateComponent6"
create_component "CreateComponent7"
create_component "CreateComponent8"
create_component "CreateComponent9"
create_component "CreateComponent10"
create_component "CreateComponent11"
create_component "CreateComponent12"
create_component "CreateComponent13"
create_component "CreateComponent14"
create_component "CreateComponent1"
create_component "CreateComponent2"
create_component "CreateComponent3"
create_component "CreateComponent4"
create_component "CreateComponent5"
create_component "CreateComponent6"
create_component "CreateComponent7"
create_component "CreateComponent8"
create_component "CreateComponent9"
create_component "CreateComponent10"
create_component "CreateComponent11"
create_component "CreateComponent12"
create_component "CreateComponent13"
create_component "CreateComponent14"
create_component "CreateComponent15"
create_component "CreateComponent16"
create_component "CreateComponent17"
create_component "CreateComponent18"
create_component "CreateComponent19"
create_component "CreateComponent20"
create_component "CreateComponent21"
create_component "CreateComponent22"
create_component "CreateComponent23"
create_component "CreateComponent24"
create_component "CreateComponent25"
create_component "CreateComponent26"
create_component "CreateComponent27"
create_component "CreateComponent28"
create_component "CreateComponent29"
create_component "CreateComponent30"
create_component "CreateComponent31"
create_component "CreateComponent32"
create_component "CreateComponent33"
create_component "CreateComponent34"
create_component "CreateComponent35"
create_component "CreateComponent1"
create_component "CreateComponent2"
create_component "CreateComponent3"
create_component "CreateComponent4"
create_component "CreateComponent5"
create_component "CreateComponent6"
create_component "CreateComponent7"
create_component "CreateComponent8"
create_component "CreateComponent9"
create_component "CreateComponent10"
create_component "CreateComponent11"
create_component "CreateComponent12" sketch "Sketch3"
create_component "CreateComponent13"
create_component "CreateComponent14"
create_component "CreateComponent15"
create_component "CreateComponent16"
create_component "CreateComponent17"
create_component "CreateComponent1"
create_component "CreateComponent2"
create_component "CreateComponent3"
create_component "CreateComponent4"
create_component "CreateComponent5"
create_component "CreateComponent6"
create_component "CreateComponent7"
create_component "CreateComponent8"
create_component "CreateComponent9"
create_component "CreateComponent10"
create_component "CreateComponent11"
create_component "CreateComponent12"
create_component "CreateComponent13"
create_component "CreateComponent14"
create_component "CreateComponent15"
create_component "CreateComponent16"
create_component "CreateComponent17"
create_component "CreateComponent18"
create_component "CreateComponent19"
create_component "CreateComponent20"
create_component "CreateComponent21"
create_component "CreateComponent22"
create_component "CreateComponent23"
create_component "CreateComponent24"
create_component "CreateComponent25"
create_component "CreateComponent26"
create_component "CreateComponent27"
create_component "CreateComponent28"
create_component "CreateComponent29"
create_component "CreateComponent30"
create_component "CreateComponent31"
create_component "CreateComponent32"
create_component "CreateComponent33"
create_component "CreateComponent34"
create_component "CreateComponent35"
create_component "CreateComponent36"
create_component "CreateComponent37"
create_component "CreateComponent38"
create_component "CreateComponent39"
create_component "CreateComponent40"
create_component "CreateComponent41"
create_component "CreateComponent42"
create_component "CreateComponent43"
create_component "CreateComponent44"
create_component "CreateComponent45"
create_component "CreateComponent46"
create_component "CreateComponent47"
create_component "CreateComponent48"
create_component "CreateComponent49"
create_component "CreateComponent50"
create_component "CreateComponent51"
create_component "CreateComponent52"
create_component "CreateComponent53"
create_component "CreateComponent54"
create_component "CreateComponent18"
create_component "CreateComponent1"
create_component "CreateComponent2"
create_component "CreateComponent3"
create_component "CreateComponent4"
create_component "CreateComponent5"
create_component "CreateComponent6"
create_component "CreateComponent7"
create_component "CreateComponent8"
create_component "CreateComponent9"
create_component "CreateComponent10"
create_component "CreateComponent11"
create_component "CreateComponent12"
create_component "CreateComponent13"
create_component "CreateComponent14"
create_component "CreateComponent15"
create_component "CreateComponent16"
create_component "CreateComponent17"
create_component "CreateComponent1"
create_component "CreateComponent2"
create_component "CreateComponent3"
create_component "CreateComponent4"
create_component "CreateComponent5"
create_component "CreateComponent6"
create_component "CreateComponent7"
create_component "CreateComponent8"
create_component "CreateComponent9"
create_component "CreateComponent10"
create_component "CreateComponent18"
create_component "CreateComponent19"
create_component "CreateComponent20"
create_component "CreateComponent21"
create_component "CreateComponent22"
create_component "CreateComponent23"
named bodies: "Cover", "Frame 1 (1) (1)", "Gears Cover", "Front Cover", "Center Frame", "Top Cover", "Center Frame", "Body1", "8mm Aluminium Pipe", "Motor", "Big Gear", "Rear Sprocket Arm Left", "Rear Sprocket Arm Right", "Rear Sprocket", "Linkage", "Small Motor Gear", "Left Center Frame", "Front Sprocket 2", "Front Sprocket 1", "Front Sprocket Spacer 2", "Body16", "Front Sprocket Spacer 1"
